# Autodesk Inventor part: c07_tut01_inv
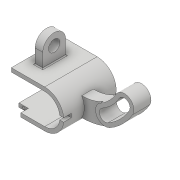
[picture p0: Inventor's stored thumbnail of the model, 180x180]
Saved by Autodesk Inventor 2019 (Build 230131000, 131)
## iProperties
Created: 2017-04
Part Number: c07_tut01_inv
Material: Generic
Document SubType Name: Modeling
Designer: CADCIM 00
Density: 1 g/cm^3
Appearance: Default
Author: CADCIM 00
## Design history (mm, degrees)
sketch "Sketch1"
  geometry: L1 (0, 16)-(35, 16); L2 (35, 16)-(35, 20); L3 (35, 20)-(0, 20); L4 (0, -20)-(35, -20); L5 (35, -20)-(35, -16); L6 (35, -16)-(0, -16); A1 r 16 centre (0, 0) between (0, 16) and (0, -16); A2 r 20 centre (0, 0) between (0, 20) and (0, -20); 1 further point
  constraints: 12 end point, 4 point on circle, 4 tangent, 3 perpendicular, 2 centre point, 2 point on line, 1 coincident, 1 concentric, 1 horizontal, 1 parallel
  dimensions: "d1" = 20 radius of A2; "d3" = 35 distance from line of point (0, 0) L5; "d37" = 16 radius of A1
extrude "Extrusion1" new body sketch "Sketch1" stored distance "d4" = 55; taper "d5" = 0 deg
sketch "Sketch2"
  geometry: A1 r 45 centre (-17.5, 55) between (-56.409, 32.393) and (-17.32, 10); A2 r 65 centre (-17.5, 55) between (-73.702, 22.345) and (-17.321, -10); A3 r 10 centre (-65.055, 27.369) between (-56.409, 32.393) and (-73.702, 22.345); A4 r 20 centre (0, 0) between (0, 20) and (0, -20) reference; A5 r 20 centre (0, 0) between (-17.32, 10) and (-17.321, -10); 1 further point
  constraints: 10 point on circle, 4 centre point, 2 tangent, 1 coincident
  dimensions: "d6" = 45 radius of A1; "d7" = 65 radius of A2; "d8" = 17.5 horizontal distance of point (0, 0) A1.centre; "d9" = 55 vertical distance of point (0, 0) A1.centre; "d10" = 60 deg dimension on A1.centre A3.centre A2.end
extrude "Extrusion2" join sketch "Sketch2" stored distance "d11" = 12; taper "d12" = 0 deg
sketch "Sketch3"
  geometry: A1 r 55 centre (-17.5, 55) between (-65.055, 27.369) and (-44.868, 7.293); A2 r 65 centre (-17.5, 55) between (-73.702, 22.345) and (-49.845, -1.381); A3 r 45 centre (-17.5, 55) between (-56.409, 32.393) and (-39.892, 15.967); A4 r 10 centre (-65.055, 27.369) between (-56.409, 32.393) and (-73.702, 22.345); A5 r 10 centre (-44.868, 7.293) between (-49.845, -1.381) and (-39.892, 15.967); A6 r 45 centre (-17.5, 55) between (-56.409, 32.393) and (-17.32, 10) reference; A7 r 65 centre (-17.5, 55) between (-73.702, 22.345) and (-17.321, -10) reference; A8 r 10 centre (-65.055, 27.369) between (-56.409, 32.393) and (-73.702, 22.345) reference; 1 further point
  constraints: 10 point on circle, 7 tangent, 5 centre point, 1 concentric
  dimensions: "d13" = 30 deg dimension on A1.centre A1.end A1.start
extrude "Extrusion3" join sketch "Sketch3" stored distance "d14" = 18; taper "d15" = 0 deg
sketch "Sketch4"
  geometry: A1 r 55 centre (17.5, 55) between (44.868, 7.293) and (65.055, 27.369); A2 r 61 centre (17.5, 55) between (47.854, 2.088) and (70.243, 24.354); A3 r 49 centre (17.5, 55) between (41.883, 12.497) and (59.867, 30.383); A4 r 6 centre (44.868, 7.293) between (41.883, 12.497) and (47.854, 2.088); A5 r 6 centre (65.055, 27.369) between (70.243, 24.354) and (59.867, 30.383); A6 r 45 centre (17.5, 55) between (39.892, 15.967) and (56.409, 32.393) reference; A7 r 10 centre (65.055, 27.369) between (73.702, 22.345) and (56.409, 32.393) reference; A8 r 10 centre (44.868, 7.293) between (39.892, 15.967) and (49.845, -1.381) reference; 1 further point
  constraints: 10 point on circle, 5 centre point, 4 tangent, 3 concentric
  dimensions: "d16" = 6 radius of A5
extrude "Extrusion4" cut sketch "Sketch4" extent not by distance; stored distance "d17" = 18; taper "d18" = 0 deg
workplane "Work Plane1"
sketch "Sketch5"
  geometry: L1 (0, 39.5)-(15, 39.5); L2 (15, 15.5)-(0, 15.5); L3 (0, 55)-(0, 0) reference; L4 (0, 39.5)-(0, 15.5); L5 (-40, 0)-(0, 0) reference; C1 r 6 at (15, 27.5); A1 r 12 centre (15, 27.5) between (15, 15.5) and (15, 39.5); 1 further point
  constraints: 6 end point, 2 centre point, 2 point on circle, 2 point on line, 2 tangent, 1 coincident, 1 collinear, 1 horizontal, 1 parallel
  dimensions: "d20" = 12 radius of A1; "d21" = 12 diameter of C1; "d22" = 15 distance from line of L3 A1.centre; "d23" = 27.5 distance from line of L5 A1.centre
extrude "Extrusion5" join sketch "Sketch5" distance "d24" = 8; taper "d25" = 0 deg
fillet "Fillet1" dims "d26" = 1
sketch "Sketch6"
  geometry: L1 (-35, -16)-(-35, -20) reference; L2 (-35, -20)-(0, -20) reference; L3 (-35, -16)-(-25, -16); L4 (-25, -16)-(-25, -20); L5 (-25, -20)-(-35, -20); L6 (-35, -20)-(-35, -16); L7 (15.631, 2)-(21.208, 2); L8 (21.208, 2)-(21.208, -2); L9 (21.208, -2)-(15.631, -2); L10 (15.631, -2)-(15.631, 2); A1 r 20 centre (0, 0) between (0, -20) and (0, 20) reference; 1 further point
  constraints: 16 end point, 4 parallel, 2 horizontal, 1 perpendicular, 1 point on line
  dimensions: "d27" = 10 distance of L1.start L3.end; "d28" = 4 distance of L9.end L7.start; "d29" = 2 distance from line of L7 point (0, 0)
extrude "Extrusion6" cut sketch "Sketch6" distance "d30" = 8; taper "d31" = 0 deg
sketch "Sketch7"
  geometry: L1 (-35, -20)-(-35, -16) reference; L2 (-25, -20)-(-35, -20) reference; C1 r 1.25 at (-30, -18); 1 further point
  constraints: 1 centre point
  dimensions: "d32" = 5 distance from line of L1 C1.centre; "d33" = 2 distance from line of L2 C1.centre; "d34" = 2.5 diameter of C1
extrude "Extrusion7" cut sketch "Sketch7" distance "d35" = 4; taper "d36" = 0 deg
body "Solid1"
other parameters: "d19" = -17.5
